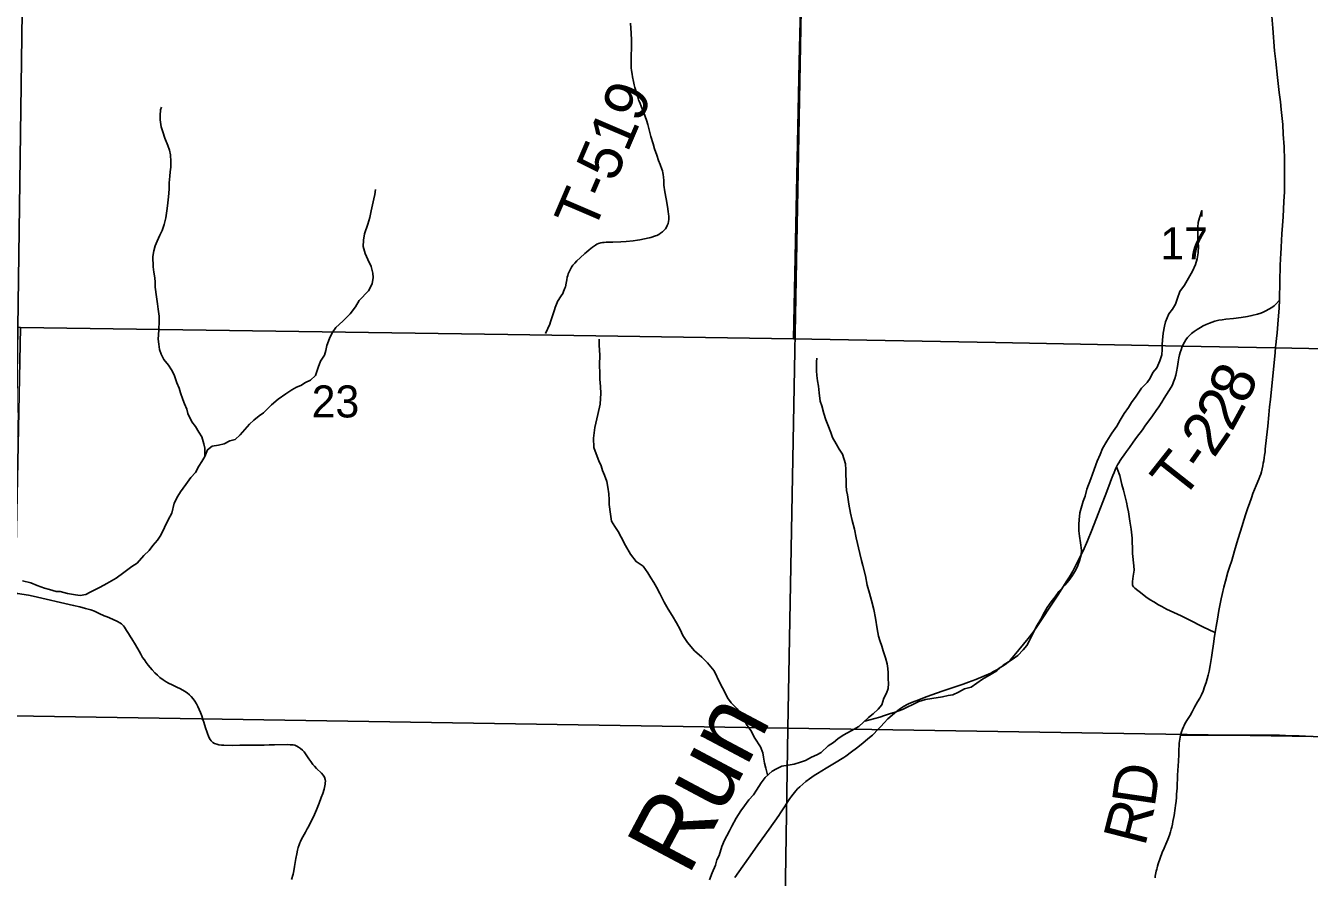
# Model space of a CAD drawing. Extents: x 0 to 34, y 0 to 22.
# Drawn here: x 20.261 to 21.94, y 18.487 to 19.601 of the extents above; entities that cross this region are included whole.
import ezdxf

# ---------------------------------------------------------------- set-up
doc = ezdxf.new("R2010")
doc.units = 0
for name, color, linetype in [('GM_X_Corporation', 7, 'Continuous'), ('GM_X_Minor_River', 7, 'Continuous'), ('GM_X_Minor_River_Text', 7, 'Continuous'), ('GM_X_Section_Text', 7, 'Continuous'), ('GM_X_Township_Road', 7, 'Continuous'), ('GM_X_Township_Road_Text', 7, 'Continuous')]:
    doc.layers.add(name, color=color, linetype=linetype)

msp = doc.modelspace()

# ---------------------------------------------------------------- linework, layer by layer
at = {"layer": 'GM_X_Corporation'}
for points in [[(21.2921, 20.4), (18.6, 20.4), (18.6, 19.2331), (18.9898, 19.2261), (20.065, 19.208), (20.254, 19.2058), (20.8916, 19.1966), (21.2652, 19.1913), (21.273, 19.5535), (21.2742, 19.6071), (21.2757, 19.6748)], [(25.4, 19.0068), (25.4, 20.4), (21.2921, 20.4), (21.2757, 19.6748), (21.2742, 19.6071), (21.273, 19.5535), (21.2652, 19.1913), (21.5297, 19.1865), (21.7744, 19.1817), (21.8956, 19.1793), (22.6423, 19.1645), (23.3329, 19.1508), (23.5499, 19.1465), (23.786, 19.1434), (24.169, 19.1418), (24.3186, 19.1409), (24.3186, 19.0261), (24.5766, 19.0222)], [(21.2769, 19.6922), (21.2582, 18.6819), (20.2437, 18.6978), (20.2574, 19.7138)], [(22.2928, 19.6778), (22.2749, 18.6656), (21.2582, 18.6819), (21.2769, 19.6922)], [(21.2582, 18.6819), (21.2422, 17.6682), (20.2237, 17.6792), (20.2437, 18.6978)], [(21.2582, 18.6819), (22.2749, 18.6656), (22.2529, 17.6514), (21.2422, 17.6682)]]:
    msp.add_lwpolyline(points, close=True, dxfattribs=at)
msp.add_lwpolyline([(25.4, 14.4307), (25.4, 19.0068), (24.5766, 19.0222), (24.3186, 19.0261), (24.3186, 19.1409), (24.169, 19.1418), (23.786, 19.1434), (23.5499, 19.1465), (23.3329, 19.1508), (22.6423, 19.1645), (21.8956, 19.1793), (21.7744, 19.1817), (21.5297, 19.1865), (21.2652, 19.1913), (20.8916, 19.1966), (20.254, 19.2058), (20.2471, 18.8539), (20.2208, 16.9558), (20.1987, 15.2691)], dxfattribs=at)
at = {"layer": 'GM_X_Minor_River'}
for points in [[(20.4386, 19.4941), (20.4374, 19.4905), (20.4367, 19.4832), (20.4368, 19.4775), (20.4381, 19.4684), (20.4401, 19.4619), (20.4429, 19.4536), (20.4468, 19.4442), (20.4491, 19.4381), (20.4504, 19.432), (20.4509, 19.4233), (20.4506, 19.4157), (20.4499, 19.4096), (20.4493, 19.4039), (20.4486, 19.3951), (20.4484, 19.3871), (20.4478, 19.3768), (20.4464, 19.365), (20.4454, 19.3585), (20.444, 19.3493), (20.4418, 19.3409), (20.4393, 19.3329), (20.4364, 19.3268), (20.4327, 19.3187), (20.4301, 19.3126), (20.4283, 19.3061), (20.4273, 19.2989), (20.4275, 19.2852), (20.4284, 19.2783), (20.4296, 19.2711), (20.4301, 19.2654), (20.4302, 19.2589), (20.4319, 19.246), (20.4331, 19.2369), (20.434, 19.2301), (20.4353, 19.2206), (20.4354, 19.2141), (20.4352, 19.2027), (20.4345, 19.1962), (20.4342, 19.1905), (20.4351, 19.184), (20.4359, 19.1772), (20.4383, 19.1711), (20.4414, 19.1643), (20.4476, 19.1568), (20.4514, 19.1508), (20.4553, 19.144), (20.4585, 19.1338), (20.4616, 19.1266), (20.4636, 19.1205), (20.4664, 19.1118), (20.4687, 19.1061), (20.4715, 19.0993), (20.4731, 19.0936), (20.4782, 19.0827), (20.4828, 19.0763), (20.4875, 19.0691), (20.4913, 19.0631), (20.4941, 19.054), (20.4953, 19.0483), (20.4953, 19.0377)], [(20.7141, 19.2632), (20.7155, 19.2712), (20.715, 19.2769), (20.713, 19.2857), (20.7083, 19.2947), (20.7048, 19.3027), (20.7024, 19.3121), (20.7026, 19.3201), (20.704, 19.3285), (20.7084, 19.3411), (20.7109, 19.3499), (20.713, 19.3587), (20.7162, 19.3744), (20.7177, 19.3801), (20.7185, 19.3863)], [(21.3586, 18.6911), (21.3785, 18.6964), (21.3845, 18.6984), (21.3909, 18.7004), (21.3985, 18.7028), (21.4079, 18.7063), (21.4143, 18.7095), (21.4214, 18.713), (21.4293, 18.7166), (21.438, 18.7193), (21.4463, 18.7206), (21.4603, 18.7227), (21.4678, 18.7244), (21.4739, 18.7256), (21.4814, 18.7288), (21.4893, 18.7331), (21.4979, 18.7355), (21.5051, 18.7405), (21.5129, 18.746), (21.5242, 18.7526), (21.5313, 18.7569), (21.5399, 18.7643), (21.5501, 18.7709), (21.5587, 18.7771), (21.5661, 18.7841), (21.5706, 18.7899), (21.5739, 18.7956), (21.5769, 18.8018), (21.5802, 18.8091), (21.5842, 18.8167), (21.589, 18.8244), (21.592, 18.8306), (21.5975, 18.8398), (21.6027, 18.8471), (21.6079, 18.8536), (21.6127, 18.8606), (21.6202, 18.869), (21.6258, 18.8748), (21.6298, 18.881), (21.6343, 18.8883), (21.6372, 18.8948), (21.6398, 18.9009), (21.6419, 18.9086), (21.6422, 18.9147), (21.641, 18.9242), (21.6397, 18.9329), (21.6388, 18.9401), (21.6387, 18.9485), (21.639, 18.9542), (21.64, 18.9637), (21.6425, 18.9729), (21.6443, 18.9786), (21.6472, 18.9855), (21.6494, 18.9947), (21.6545, 19.0081), (21.6589, 19.0204), (21.6625, 19.0311), (21.6665, 19.0399), (21.6698, 19.0475), (21.6754, 19.0571), (21.682, 19.0679), (21.6883, 19.0771), (21.6927, 19.0848), (21.6979, 19.0933), (21.7039, 19.1013), (21.7076, 19.1079), (21.7139, 19.116), (21.7209, 19.1267), (21.728, 19.1341), (21.7321, 19.1398), (21.7354, 19.1471), (21.7406, 19.1533), (21.7446, 19.1625), (21.7472, 19.1701), (21.7478, 19.177), (21.7477, 19.1838), (21.748, 19.1896), (21.749, 19.1987), (21.7508, 19.2075), (21.7522, 19.2132), (21.7566, 19.2239), (21.7614, 19.2301), (21.7651, 19.2366), (21.768, 19.2443), (21.7709, 19.2531), (21.7769, 19.2612), (21.7824, 19.2704), (21.7876, 19.2796), (21.7912, 19.2884), (21.7934, 19.2957), (21.7948, 19.3037), (21.7951, 19.3128), (21.7946, 19.3193), (21.7943, 19.3372), (21.795, 19.3433), (21.7964, 19.3494), (21.7997, 19.359), (21.7998, 19.3513)], [(20.2567, 18.8746), (20.2677, 18.8718), (20.2757, 18.8684), (20.2856, 18.8652), (20.2921, 18.8634), (20.3005, 18.8608), (20.3061, 18.8605), (20.3156, 18.858), (20.3259, 18.8563), (20.3323, 18.8556), (20.3395, 18.8568), (20.3451, 18.8596), (20.3583, 18.8662), (20.3669, 18.8709), (20.379, 18.878), (20.3891, 18.8854), (20.3999, 18.8935), (20.4067, 18.8978), (20.4152, 18.9078), (20.4223, 18.9144), (20.4272, 18.9206), (20.4335, 18.9279), (20.4376, 18.9344), (20.4471, 18.9543), (20.4519, 18.9632), (20.4551, 18.9762), (20.4599, 18.9854), (20.4636, 18.9911), (20.4703, 19.0007), (20.477, 19.0096), (20.4829, 19.0162), (20.4874, 19.0246), (20.4911, 19.0307), (20.4951, 19.0373), (20.4988, 19.0461), (20.5048, 19.0507), (20.5131, 19.052), (20.5206, 19.0536), (20.5281, 19.0576), (20.5349, 19.0596), (20.5413, 19.0657), (20.5536, 19.0793), (20.5592, 19.0847), (20.5663, 19.0905), (20.5719, 19.0944), (20.5824, 19.1048), (20.5913, 19.1122), (20.6011, 19.1192), (20.6089, 19.1246), (20.6153, 19.1281), (20.621, 19.1301), (20.627, 19.134), (20.6334, 19.1372), (20.6401, 19.143), (20.6437, 19.1537), (20.6466, 19.1621), (20.6518, 19.1698), (20.6536, 19.1759), (20.6547, 19.1824), (20.6583, 19.1916), (20.6616, 19.1989), (20.6668, 19.2058), (20.6758, 19.2143), (20.6855, 19.224), (20.6922, 19.2328), (20.6973, 19.2413), (20.7093, 19.254), (20.7141, 19.2632)], [(21.2315, 18.621), (21.2292, 18.6294), (21.2275, 18.6362), (21.2263, 18.6438), (21.2251, 18.6495), (21.2223, 18.6574), (21.215, 18.6687), (21.2095, 18.6786), (21.2041, 18.6868), (21.1982, 18.6978), (21.1917, 18.7072), (21.184, 18.7151), (21.179, 18.7215), (21.1762, 18.7279), (21.1692, 18.7411), (21.1614, 18.757), (21.1529, 18.7675), (21.1453, 18.7746), (21.136, 18.7829), (21.1268, 18.7938), (21.1206, 18.8032), (21.1171, 18.8107), (21.1124, 18.8198), (21.1066, 18.8292), (21.1015, 18.8375), (21.0961, 18.8466), (21.0907, 18.8579), (21.086, 18.8662), (21.0825, 18.8726), (21.0786, 18.8783), (21.0747, 18.8851), (21.0685, 18.8937), (21.0594, 18.8997), (21.052, 18.9095), (21.0458, 18.9208), (21.04, 18.9317), (21.0361, 18.9389), (21.0318, 18.9457), (21.0275, 18.9528), (21.0259, 18.9616), (21.0242, 18.9745), (21.0241, 18.9806), (21.0236, 18.9882), (21.0227, 18.9969), (21.0211, 19.0045), (21.0183, 19.0128), (21.0156, 19.0189), (21.0136, 19.0249), (21.0105, 19.0314), (21.0073, 19.0405), (21.0042, 19.0492), (21.0036, 19.061), (21.0053, 19.0751), (21.0092, 19.0922), (21.0124, 19.1056), (21.0131, 19.1132), (21.0134, 19.1197), (21.0129, 19.1288), (21.012, 19.1383), (21.0119, 19.1456), (21.0117, 19.157), (21.0119, 19.1699), (21.0118, 19.1764), (21.0113, 19.1829), (21.0112, 19.1908)], [(21.3001, 19.1096), (21.2988, 19.1206), (21.298, 19.1294), (21.2967, 19.1362), (21.2959, 19.1431), (21.2954, 19.1491), (21.2953, 19.1552), (21.2956, 19.1609), (21.296, 19.1657)], [(21.1556, 18.4833), (21.1592, 18.4928), (21.1632, 18.5028), (21.165, 18.5097), (21.168, 18.5154), (21.1716, 18.5269), (21.1753, 18.5353), (21.1782, 18.5411), (21.1815, 18.5476), (21.1848, 18.5537), (21.1904, 18.5641), (21.1967, 18.5737), (21.2011, 18.5802), (21.207, 18.5883), (21.213, 18.5945), (21.2171, 18.6007), (21.223, 18.6103), (21.2282, 18.6172), (21.2375, 18.6257), (21.2432, 18.6288), (21.2503, 18.632), (21.2586, 18.6336), (21.2662, 18.6349), (21.2745, 18.6373), (21.2813, 18.6397), (21.2891, 18.644), (21.2959, 18.6468), (21.3016, 18.6499), (21.3109, 18.6588), (21.3176, 18.6631), (21.3236, 18.6681), (21.3304, 18.6728), (21.3409, 18.6783), (21.351, 18.6841), (21.357, 18.6896), (21.3634, 18.6958), (21.3697, 18.7008), (21.3761, 18.7066), (21.3809, 18.7124), (21.3834, 18.7212), (21.3871, 18.7277), (21.3893, 18.7338), (21.3896, 18.7403), (21.3891, 18.7464), (21.3894, 18.7544), (21.3889, 18.7601), (21.3881, 18.7658), (21.3857, 18.7737), (21.3829, 18.7832), (21.3809, 18.7893), (21.3782, 18.7965), (21.3766, 18.8021), (21.3749, 18.8116), (21.3728, 18.8257), (21.3704, 18.8371), (21.3676, 18.8488), (21.3648, 18.8583), (21.362, 18.8689), (21.3595, 18.881), (21.3563, 18.8947), (21.3543, 18.9011), (21.3523, 18.9102), (21.3474, 18.9307), (21.3454, 18.9421), (21.3422, 18.9535), (21.3398, 18.9633), (21.3377, 18.9747), (21.336, 18.9869), (21.3348, 18.9926), (21.3343, 18.9994), (21.334, 19.0196), (21.3335, 19.0275), (21.3295, 19.0404), (21.3253, 19.0468), (21.3214, 19.0536), (21.3164, 19.0619), (21.3144, 19.0687), (21.3104, 19.0786), (21.3077, 19.085), (21.3053, 19.0933), (21.3025, 19.1036), (21.3001, 19.1096)]]:
    msp.add_lwpolyline(points, dxfattribs=at)
at = {"layer": 'GM_X_Township_Road'}
for points in [[(21.9013, 19.2419), (21.9019, 19.2671), (21.9022, 19.2862), (21.9027, 19.2965), (21.9029, 19.3019), (21.9034, 19.311), (21.9039, 19.3196), (21.9044, 19.3286), (21.9051, 19.3395), (21.9059, 19.3507), (21.907, 19.3709), (21.9077, 19.3835), (21.9079, 19.3957), (21.9076, 19.4248), (21.9072, 19.4421), (21.9061, 19.459), (21.9055, 19.4717), (21.9036, 19.4913), (21.9025, 19.5012), (21.9009, 19.5132), (21.8987, 19.5328), (21.8963, 19.5538), (21.8949, 19.5679), (21.8925, 19.5977), (21.891, 19.6186)], [(20.9411, 19.1981), (20.9465, 19.2105), (20.9476, 19.2135), (20.9525, 19.2289), (20.9536, 19.2322), (20.9561, 19.2387), (20.9568, 19.24), (20.9616, 19.2475), (20.9634, 19.2505), (20.9646, 19.2529), (20.9664, 19.2574), (20.9669, 19.2592), (20.9678, 19.2638), (20.9687, 19.2684), (20.9694, 19.2716), (20.97, 19.2739), (20.9707, 19.2761), (20.9715, 19.2781), (20.9732, 19.2816), (20.9751, 19.2848), (20.9769, 19.2875), (20.9791, 19.2902), (20.9818, 19.293), (20.9864, 19.2972), (20.9923, 19.3026), (20.9944, 19.3044), (20.9982, 19.3075), (21.0026, 19.311), (21.0063, 19.3136), (21.0083, 19.3148), (21.0103, 19.3157), (21.0133, 19.3166), (21.0153, 19.317), (21.0175, 19.3172), (21.0205, 19.3174), (21.0243, 19.3175), (21.0289, 19.3176), (21.0394, 19.318), (21.0466, 19.3184), (21.0557, 19.3193), (21.0612, 19.3201), (21.0645, 19.3207), (21.0767, 19.3232), (21.0788, 19.3238), (21.0849, 19.3258), (21.0867, 19.3265), (21.0893, 19.3278), (21.0915, 19.3292), (21.094, 19.3312), (21.0962, 19.3331), (21.0979, 19.3349), (21.0991, 19.3372), (21.1003, 19.3393), (21.1013, 19.3422), (21.1019, 19.3445), (21.1021, 19.3473), (21.1023, 19.35), (21.1022, 19.3516), (21.1019, 19.3543), (21.1015, 19.3578), (21.1007, 19.3642), (21.0988, 19.3743), (21.0971, 19.3834), (21.0965, 19.3865), (21.0962, 19.3893), (21.0959, 19.3923), (21.0958, 19.3955), (21.0957, 19.3984), (21.0953, 19.4027), (21.095, 19.4063), (21.0946, 19.4082), (21.0938, 19.411), (21.093, 19.4132), (21.0908, 19.4191), (21.0887, 19.4245), (21.0864, 19.4314), (21.0837, 19.4395), (21.0817, 19.4462), (21.0789, 19.4558), (21.0772, 19.4626), (21.0747, 19.4717), (21.073, 19.4771), (21.0712, 19.482), (21.0695, 19.4868), (21.068, 19.4908), (21.0661, 19.4957), (21.0647, 19.4991), (21.0635, 19.502), (21.0628, 19.5038), (21.0617, 19.5072), (21.0605, 19.511), (21.0594, 19.5148), (21.058, 19.5197), (21.057, 19.5234), (21.056, 19.5277), (21.0548, 19.534), (21.0542, 19.5375), (21.0538, 19.5397), (21.0535, 19.5425), (21.0532, 19.5453), (21.053, 19.5475), (21.0531, 19.5623), (21.0533, 19.5709), (21.0534, 19.5767), (21.0533, 19.5819), (21.0531, 19.591), (21.0527, 19.5975), (21.052, 19.6042)], [(21.7749, 19.1827), (21.777, 19.1867), (21.7789, 19.1897), (21.7811, 19.1928), (21.7838, 19.1959), (21.7863, 19.1981), (21.7896, 19.2007), (21.7935, 19.2035), (21.798, 19.2061), (21.8015, 19.208), (21.8055, 19.2099), (21.8096, 19.2118), (21.8168, 19.2144), (21.8221, 19.2155), (21.8264, 19.2162), (21.8311, 19.2168), (21.8412, 19.2179), (21.8511, 19.2192), (21.8593, 19.2204), (21.8652, 19.2216), (21.8724, 19.2236), (21.8769, 19.2249), (21.8801, 19.2262), (21.8835, 19.2278), (21.8872, 19.2298), (21.8911, 19.2322), (21.8941, 19.2344), (21.8966, 19.2366), (21.9013, 19.2419)], [(21.8961, 19.1807), (21.8964, 19.1834), (21.8973, 19.1915), (21.898, 19.1989), (21.8991, 19.2104), (21.9007, 19.2316), (21.9013, 19.2419)], [(21.693, 19.0322), (21.6945, 19.0345), (21.6979, 19.0395), (21.701, 19.0437), (21.7048, 19.0489), (21.7099, 19.0558), (21.7142, 19.0622), (21.7219, 19.0719), (21.7261, 19.078), (21.7302, 19.0839), (21.7351, 19.0906), (21.7399, 19.0972), (21.7433, 19.1024), (21.7472, 19.1083), (21.7505, 19.1135), (21.7597, 19.1279), (21.7613, 19.131), (21.7628, 19.1348), (21.7644, 19.1393), (21.7656, 19.1438), (21.7664, 19.148), (21.7676, 19.1548), (21.7686, 19.1612), (21.7694, 19.1662), (21.7703, 19.1704), (21.7712, 19.1733), (21.7724, 19.1766), (21.7734, 19.1796), (21.7749, 19.1827)], [(21.817, 18.8071), (21.8185, 18.8149), (21.8202, 18.8246), (21.8219, 18.8357), (21.8249, 18.8512), (21.8261, 18.8566), (21.8285, 18.8663), (21.8305, 18.8743), (21.8338, 18.8857), (21.836, 18.8925), (21.8387, 18.9013), (21.8424, 18.9138), (21.8469, 18.9286), (21.8502, 18.9394), (21.8569, 18.9611), (21.8582, 18.965), (21.8599, 18.97), (21.8619, 18.9758), (21.8646, 18.9831), (21.8665, 18.9886), (21.8709, 18.9993), (21.8743, 19.0077), (21.8756, 19.011), (21.8767, 19.0143), (21.8775, 19.0173), (21.8784, 19.0212), (21.8793, 19.0251), (21.88, 19.0284), (21.8807, 19.0315), (21.8813, 19.0356), (21.8818, 19.0391), (21.8823, 19.0434), (21.8827, 19.047), (21.8842, 19.0621), (21.8858, 19.0769), (21.8874, 19.0917), (21.8884, 19.1021), (21.8894, 19.1116), (21.8954, 19.1733), (21.8961, 19.1807)], [(21.6881, 19.0236), (21.6894, 19.0262), (21.691, 19.0291), (21.693, 19.0322)], [(21.1885, 18.4864), (21.2117, 18.5194), (21.2186, 18.5292), (21.2334, 18.5498), (21.2461, 18.5675), (21.2485, 18.5711), (21.2543, 18.5802), (21.2581, 18.5861), (21.2606, 18.5897), (21.2621, 18.5918), (21.2649, 18.5956), (21.2685, 18.5999), (21.2708, 18.6024), (21.2737, 18.6053), (21.2776, 18.6087), (21.2816, 18.6119), (21.2863, 18.6154), (21.2924, 18.6198), (21.2967, 18.6226), (21.3081, 18.6295), (21.3189, 18.6361), (21.3312, 18.6435), (21.334, 18.6454), (21.3411, 18.6507), (21.3478, 18.6558), (21.3561, 18.6624), (21.3626, 18.6678), (21.3686, 18.6728), (21.3705, 18.6746), (21.375, 18.6791), (21.3798, 18.6841), (21.384, 18.6888), (21.3888, 18.6939), (21.3913, 18.6962), (21.398, 18.7021), (21.3997, 18.7034), (21.4043, 18.7066), (21.4095, 18.71), (21.4149, 18.7131), (21.4199, 18.7155), (21.4258, 18.7178), (21.4404, 18.7233), (21.4526, 18.7277), (21.4614, 18.7306), (21.4874, 18.7394), (21.4943, 18.742), (21.504, 18.7456), (21.5154, 18.7505), (21.5234, 18.754), (21.5272, 18.756), (21.5322, 18.7588), (21.5359, 18.761), (21.5399, 18.7635), (21.5441, 18.7664), (21.5468, 18.7686), (21.5488, 18.7709), (21.5513, 18.7737), (21.554, 18.7769), (21.5723, 18.7991), (21.5788, 18.8076), (21.5847, 18.8157), (21.59, 18.8237), (21.6027, 18.8428), (21.6114, 18.8558), (21.6187, 18.8674), (21.6222, 18.8731), (21.6263, 18.8797), (21.6307, 18.8872), (21.6339, 18.8932), (21.6376, 18.9003), (21.6444, 18.914), (21.6501, 18.9269), (21.6558, 18.9408), (21.664, 18.9621), (21.6703, 18.978), (21.6753, 18.9915), (21.6797, 19.0033), (21.6815, 19.0082), (21.6831, 19.0124), (21.6848, 19.0165), (21.6863, 19.0198), (21.6881, 19.0236)], [(21.817, 18.8071), (21.8111, 18.8098), (21.7994, 18.8154), (21.7848, 18.8228), (21.7728, 18.8286), (21.7582, 18.8354), (21.7536, 18.8376), (21.7475, 18.8408), (21.7429, 18.8433), (21.7367, 18.847), (21.7321, 18.8499), (21.7265, 18.8537), (21.7215, 18.8574), (21.7122, 18.8648), (21.7112, 18.8658), (21.7101, 18.8669), (21.7094, 18.8679), (21.709, 18.8689), (21.7089, 18.8699), (21.7089, 18.8736), (21.7099, 18.8805), (21.711, 18.8886), (21.7107, 18.8942), (21.7088, 18.9103), (21.7088, 18.9124), (21.7087, 18.9305), (21.7072, 18.9422), (21.7056, 18.9527), (21.7046, 18.9589), (21.7036, 18.9647), (21.7024, 18.9706), (21.7009, 18.9774), (21.6987, 18.9863), (21.697, 18.9931), (21.6952, 19.0004), (21.6923, 19.0122), (21.6916, 19.0144), (21.6888, 19.0217), (21.6881, 19.0236)], [(20.2643, 18.8557), (20.2557, 18.8572), (20.2504, 18.8579), (20.2461, 18.8581), (20.2452, 18.8582)], [(20.3675, 18.8273), (20.3637, 18.829), (20.357, 18.832), (20.3507, 18.8348), (20.3459, 18.8365), (20.339, 18.8385), (20.3318, 18.8404), (20.3234, 18.8425), (20.2708, 18.8543), (20.2643, 18.8557)], [(20.6204, 18.5338), (20.6213, 18.5357), (20.6233, 18.5396), (20.6269, 18.5459), (20.6291, 18.5501), (20.6311, 18.5538), (20.6388, 18.569), (20.6413, 18.5749), (20.6448, 18.5837), (20.6475, 18.591), (20.6495, 18.5962), (20.6514, 18.6021), (20.6527, 18.6087), (20.6528, 18.6102), (20.6529, 18.6127), (20.6526, 18.6148), (20.6516, 18.6177), (20.6499, 18.6205), (20.6479, 18.6229), (20.6414, 18.6289), (20.6386, 18.632), (20.6366, 18.6343), (20.6341, 18.6382), (20.6315, 18.6418), (20.6276, 18.6471), (20.625, 18.6507), (20.6228, 18.6531), (20.6206, 18.6551), (20.6177, 18.6572), (20.6156, 18.6585), (20.6131, 18.6595), (20.6106, 18.66), (20.6069, 18.6602), (20.6037, 18.6604), (20.5863, 18.6602), (20.5796, 18.6599), (20.5729, 18.6598), (20.566, 18.6597), (20.549, 18.6596), (20.5412, 18.6595), (20.532, 18.6593), (20.5199, 18.6595), (20.517, 18.6597), (20.5137, 18.6601), (20.5108, 18.6608), (20.5079, 18.6619), (20.5057, 18.6631), (20.5035, 18.6651), (20.502, 18.6672), (20.5006, 18.6701), (20.4983, 18.6762), (20.4963, 18.6822), (20.494, 18.6896), (20.4928, 18.6934), (20.4911, 18.6981), (20.4896, 18.7022), (20.4877, 18.7063), (20.4859, 18.7104), (20.4844, 18.7135), (20.4823, 18.7173), (20.4801, 18.7204), (20.4775, 18.7234), (20.4751, 18.7255), (20.4721, 18.728), (20.4684, 18.7304), (20.4634, 18.7332), (20.4588, 18.7355), (20.4523, 18.7386), (20.4479, 18.7406), (20.4446, 18.7426), (20.4408, 18.745), (20.4364, 18.7482), (20.4331, 18.7512), (20.4298, 18.7543), (20.4264, 18.758), (20.4236, 18.7611), (20.421, 18.7644), (20.4183, 18.7678), (20.4161, 18.7711), (20.4138, 18.7745), (20.4114, 18.7786), (20.4095, 18.7824), (20.4045, 18.7907), (20.3998, 18.7985), (20.3981, 18.8015), (20.3955, 18.8056), (20.3929, 18.8098), (20.3902, 18.8138), (20.3888, 18.8157), (20.3875, 18.8171), (20.3861, 18.8182), (20.3841, 18.8196), (20.3811, 18.8212), (20.3742, 18.8243), (20.3675, 18.8273)], [(21.7719, 18.6729), (21.7731, 18.6769), (21.7744, 18.6806), (21.7755, 18.6834), (21.7765, 18.6854), (21.778, 18.6882), (21.7807, 18.693), (21.7842, 18.6986), (21.7869, 18.7033), (21.7902, 18.7093), (21.7941, 18.7165), (21.7969, 18.7213), (21.7992, 18.7256), (21.8012, 18.7301), (21.8033, 18.7357), (21.8052, 18.7416), (21.8065, 18.7463), (21.8079, 18.751), (21.8092, 18.7564), (21.8106, 18.764), (21.8123, 18.7742), (21.8132, 18.7806), (21.8148, 18.7922), (21.8163, 18.8022), (21.817, 18.8071)], [(21.7385, 18.486), (21.7386, 18.4884), (21.739, 18.4905), (21.7395, 18.4928), (21.74, 18.4948), (21.7406, 18.4975), (21.7411, 18.4992), (21.7417, 18.5015), (21.7427, 18.5045), (21.7479, 18.519), (21.7503, 18.5249), (21.7525, 18.5301), (21.7551, 18.5362), (21.7572, 18.5418), (21.7585, 18.5461), (21.7597, 18.5499), (21.7604, 18.5525), (21.7611, 18.5562), (21.7618, 18.5597), (21.7634, 18.5678), (21.7648, 18.5772), (21.7652, 18.5809), (21.7659, 18.5865), (21.7663, 18.5911), (21.7666, 18.5954), (21.7669, 18.5996), (21.7672, 18.6035), (21.7674, 18.6089), (21.7677, 18.615), (21.768, 18.6201), (21.7684, 18.6269), (21.7688, 18.632), (21.7691, 18.6389), (21.7694, 18.6469), (21.7696, 18.655), (21.7698, 18.6581), (21.77, 18.6622), (21.7703, 18.6648), (21.7707, 18.6673), (21.7712, 18.67), (21.7719, 18.6729)], [(21.9429, 18.671), (21.9351, 18.6713), (21.9272, 18.6716), (21.909, 18.6723), (21.9011, 18.6726), (21.8914, 18.6728), (21.8129, 18.6726), (21.7853, 18.6727), (21.7742, 18.6728), (21.7719, 18.6729)], [(20.6085, 18.4837), (20.6106, 18.4907), (20.6115, 18.4951), (20.6126, 18.5011), (20.6144, 18.5112), (20.6155, 18.5173), (20.6166, 18.5223), (20.6174, 18.5256), (20.6186, 18.5294), (20.6196, 18.532), (20.6204, 18.5338)]]:
    msp.add_lwpolyline(points, dxfattribs=at)

# ---------------------------------------------------------------- texts
at = {"layer": 'GM_X_Minor_River_Text'}
msp.add_text('Run', height=0.09468, rotation=62.0124, dxfattribs=at).set_placement((21.1276, 18.487))
at = {"layer": 'GM_X_Section_Text'}
for s, p in [('17', (21.7454, 19.2951)), ('23', (20.635, 19.0883))]:
    msp.add_text(s, height=0.04186, rotation=0, dxfattribs=at).set_placement(p)
at = {"layer": 'GM_X_Township_Road_Text'}
for s, height, rotation, p in [('T-519', 0.05682, 66.8344, (21.0033, 19.3288)), ('8', 0.0568, 65.9689, (21.8577, 19.1035)), ('2', 0.0568, 61.391, (21.8388, 19.0684)), ('2', 0.0568, 55.3629, (21.8154, 19.034)), ('T', 0.0568, 51.6789, (21.7734, 18.9783)), ('-', 0.0568, 55.1436, (21.802, 19.0147)), ('D', 0.0568, 81.7076, (21.7378, 18.5774)), ('R', 0.0568, 75.7157, (21.7251, 18.5259))]:
    msp.add_text(s, height=height, rotation=rotation, dxfattribs=at).set_placement(p)

doc.saveas('drawing.dxf')
